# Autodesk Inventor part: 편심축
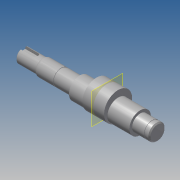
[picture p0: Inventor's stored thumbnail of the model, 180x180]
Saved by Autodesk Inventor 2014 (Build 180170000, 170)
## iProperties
Created: 2015-12
Part Number: 편심축
Material: 강철, 연강
Document SubType Name: Modeling
Designer: mduedu
Density: 7.86 g/cm^3
Appearance: 강철
Author: mduedu
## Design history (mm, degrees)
sketch "스케치1"
  geometry: L1 (-62.5, 0)-(62.5, 0); L2 (-62.5, 0)-(-62.5, 6.5); L3 (-62.5, 6.5)-(-43.5, 6.5); L4 (-43.5, 7)-(-42.634, 7.5); L5 (-42.634, 7.5)-(-9.5, 7.5); L6 (-9.5, 7.5)-(-9.5, 10); L7 (-9.5, 10)-(46.5, 10); L8 (46.5, 10)-(46.5, 7.5); L9 (46.5, 7.5)-(62.5, 7.5); L10 (62.5, 7.5)-(62.5, 0); L11 (-43.5, 6.5)-(-43.5, 7); 2 further points
  constraints: 22 end point, 6 parallel, 2 perpendicular, 1 coincident, 1 horizontal, 1 midpoint, 1 vertical
  dimensions: "d0" = 13 diameter of L3 L1; "d2" = 15 diameter of L5 L1; "d3" = 20 diameter of L7 L1; "d5" = 15 diameter of L9 L1; "d6" = 125 distance of L1.start L1.end; "d7" = 19 distance of L2.end L3.end; "d8" = 34 distance from line of L6 L3.end; "d9" = 56 distance of L6.end L7.end; "d41" = 14 diameter of L4.start L1; "d42" = 30 deg angle of L4 L3
revolve "회전1" sketch "스케치1" stored, may be unused: angle "d11" = 90 deg
node "작업 평면1"
sketch "스케치2"
  geometry: C1 r 13 at (0, 3); 1 further point
  constraints: 1 centre point, 1 vertical alignment
  dimensions: "d13" = 26 diameter of C1; "d14" = 3 distance of point (0, 0) C1.centre
extrude "돌출1" join sketch "스케치2" distance "d15" = 20; taper "d16" = 0 deg
node "작업 평면2"
sketch "스케치3"
  geometry: L1 (9.5, -2.5)-(-2.5, -2.5); L2 (-2.5, 2.5)-(9.5, 2.5); L3 (9.5, 2.5)-(9.5, -2.5); L4 (9.5, 6.5)-(9.5, -6.5) reference; A1 r 2.5 centre (-2.5, 0) between (-2.5, 2.5) and (-2.5, -2.5); 1 further point
  constraints: 6 end point, 2 point on circle, 2 tangent, 1 centre point, 1 collinear, 1 horizontal, 1 horizontal alignment, 1 parallel
  dimensions: "d17" = 5 distance of L2.end L1.start; "d19" = 12 distance from line of A1.centre L3
extrude "돌출2" cut sketch "스케치3" distance "d20" = 3; taper "d21" = 0 deg
chamfer "모따기1" distance "d22" = 1; stored, may be unused: second distance "d23" = 2, angle "d24" = 45 deg
fillet "모깎기1" dims "d25" = 3
sketch "스케치4"
  geometry: L1 (-9.5, -10)-(-9.5, 10) reference; L2 (-9.5, 0)-(0, 0); L3 (-26.65, 12.15)-(-25.5, 12.15); L4 (-25.5, 12.15)-(-25.5, 7.15); L5 (-25.5, 7.15)-(-26.65, 7.15); L6 (-26.65, 7.15)-(-26.65, 12.15); L7 (57.5, 12.15)-(58.65, 12.15); L8 (58.65, 12.15)-(58.65, 7.15); L9 (58.65, 7.15)-(57.5, 7.15); L10 (57.5, 7.15)-(57.5, 12.15); L11 (62.5, -7.5)-(62.5, 7.5) reference
  constraints: 18 end point, 4 parallel, 2 horizontal, 2 perpendicular, 1 midpoint
  dimensions: "d26" = 16 distance between parallel lines of L4 L1; "d27" = 1.15 distance of L3.start L3.end; "d28" = 14.3 diameter of L5 L2; "d29" = 5 distance of L3.end L4.end; "d30" = 1.15 distance of L7.start L7.end; "d31" = 5 distance of L7.end L8.end; "d32" = 5 distance between parallel lines of L10 L11; "d33" = 14.3 diameter of L9 L2
revolve "회전2" sketch "스케치4" stored, may be unused: angle "d34" = 90 deg
chamfer "모따기2" distance "d35" = 1; stored, may be unused: second distance "d36" = 2, angle "d37" = 45 deg
fillet "모깎기2" dims "d38" = 0.3
sketch "스케치5"
  geometry: 2 further points
  constraints: 1 coincident
sketch "스케치6"
  geometry: 1 further point
hole "구멍1" sketch "스케치6" at (2.5, -3.5) diameter "d43" = 4.917; stored, may be unused: countersink angle "d47" = 90 deg, drill point angle "d49" = 120 deg; dims "d44" = 14, "d45" = 4, "d46" = 2, "d48" = 17
node "작업 평면3"
node "솔리드1"
other parameters: "d12" = -15.5
